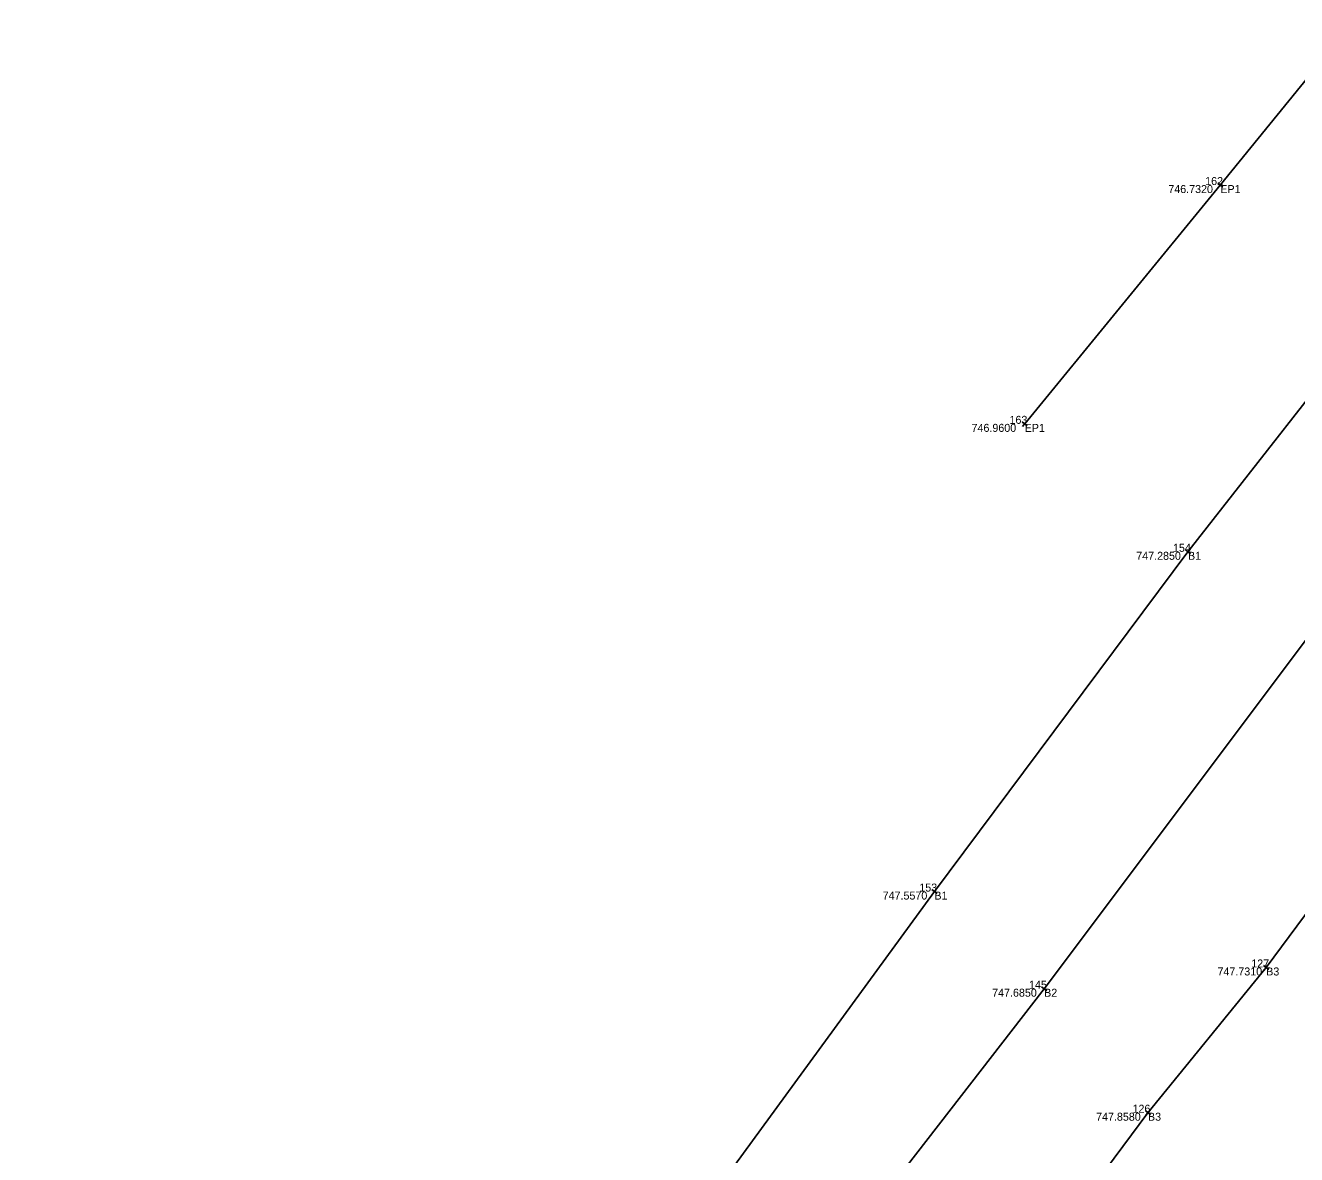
# Model space of a CAD drawing. Extents: x 1857337 to 1857837, y 693958 to 694371.
# Drawn here: x 1857509.4 to 1857604.7, y 694201.5 to 694286.2 of the extents above; entities that cross this region are included whole.
import ezdxf

# ---------------------------------------------------------------- set-up
doc = ezdxf.new("R2010")
doc.units = 0
for name, color, linetype in [('BR_X_SV_Pier_Cap_Bottom', 7, 'Continuous'), ('SV_X_Random_Point', 7, 'Continuous'), ('SV_X_Text_Comment', 7, 'Continuous'), ('SV_X_Text_Description', 7, 'Continuous'), ('SV_X_Text_Name', 7, 'Continuous'), ('UT_X_Electric_Cells', 7, 'Continuous')]:
    doc.layers.add(name, color=color, linetype=linetype)

msp = doc.modelspace()

# ---------------------------------------------------------------- linework, layer by layer
at = {"layer": 'BR_X_SV_Pier_Cap_Bottom'}
for p, q in [((1857599.173, 694274.033), (1857598.785, 694274.349)), ((1857599.137, 694274.385), (1857598.821, 694273.997)), ((1857598.979, 694274.191), (1857598.979, 694274.191)), ((1857584.508, 694256.125), (1857584.122, 694256.441)), ((1857584.473, 694256.476), (1857584.157, 694256.09)), ((1857584.315, 694256.283), (1857584.315, 694256.283)), ((1857596.755, 694246.534), (1857596.361, 694246.842)), ((1857596.712, 694246.885), (1857596.404, 694246.491)), ((1857596.558, 694246.688), (1857596.558, 694246.688)), ((1857577.747, 694221.059), (1857577.347, 694221.358)), ((1857577.697, 694221.408), (1857577.397, 694221.008)), ((1857577.547, 694221.208), (1857577.547, 694221.208)), ((1857602.621, 694215.368), (1857602.219, 694215.666)), ((1857602.569, 694215.718), (1857602.271, 694215.316)), ((1857602.42, 694215.517), (1857602.42, 694215.517)), ((1857585.974, 694213.773), (1857585.574, 694214.073)), ((1857585.924, 694214.123), (1857585.624, 694213.723)), ((1857585.774, 694213.923), (1857585.774, 694213.923)), ((1857593.751, 694204.465), (1857593.363, 694204.781)), ((1857593.715, 694204.817), (1857593.399, 694204.429)), ((1857593.557, 694204.623), (1857593.557, 694204.623))]:
    msp.add_line(p, q, dxfattribs=at)
at = {"layer": 'SV_X_Random_Point'}
msp.add_lwpolyline([(1857678.612, 694370.843), (1857656.803, 694344.014), (1857632.513, 694313.441), (1857612.984, 694291.43), (1857598.979, 694274.191), (1857584.315, 694256.283)], dxfattribs=at)
at = {"layer": 'UT_X_Electric_Cells'}
for points in [[(1857688.755, 694366.464), (1857664.256, 694336.576), (1857640.398, 694304.002), (1857624.286, 694283.662), (1857611.111, 694265.289), (1857596.558, 694246.688), (1857577.547, 694221.208), (1857552.759, 694187.231), (1857529.482, 694157.726), (1857506.444, 694129.202)], [(1857700.074, 694362.042), (1857689.247, 694348.993), (1857682.836, 694339.855), (1857667.65, 694320.725), (1857658.449, 694307.697), (1857647.304, 694293.665), (1857639.922, 694285.279), (1857631.254, 694272.579), (1857620.537, 694259.563), (1857609.95, 694246.134), (1857585.774, 694213.923), (1857569.943, 694193.463), (1857560.421, 694180.388), (1857538.657, 694151.419), (1857515.128, 694123.122)], [(1857711.16, 694357.223), (1857703.201, 694345.955), (1857690.712, 694330.845), (1857675.141, 694311.606), (1857665.25, 694297.054), (1857650.194, 694279.109), (1857639.816, 694265.056), (1857626.459, 694247.565), (1857616.276, 694234.207), (1857602.42, 694215.517), (1857593.557, 694204.623), (1857579.141, 694185.197), (1857570.864, 694174.066), (1857548.438, 694145.748), (1857525.385, 694115.504)]]:
    msp.add_lwpolyline(points, dxfattribs=at)

# ---------------------------------------------------------------- texts
at = {"layer": 'SV_X_Text_Comment'}
for s, p in [('EP1', (1857598.979, 694273.591)), ('EP1', (1857584.315, 694255.683)), ('B1', (1857596.558, 694246.088)), ('B1', (1857577.547, 694220.608)), ('B3', (1857602.42, 694214.917)), ('B2', (1857585.774, 694213.323)), ('B3', (1857593.557, 694204.023))]:
    msp.add_text(s, height=0.6, dxfattribs=at).set_placement(p)
at = {"layer": 'SV_X_Text_Description'}
for s, p in [('746.7320', (1857595.082, 694273.591)), ('746.9600', (1857580.333, 694255.683)), ('747.2850', (1857592.68, 694246.088)), ('747.5570', (1857573.669, 694220.608)), ('747.7310', (1857598.769, 694214.917)), ('747.6850', (1857581.877, 694213.323)), ('747.8580', (1857589.669, 694204.023))]:
    msp.add_text(s, height=0.6, dxfattribs=at).set_placement(p)
at = {"layer": 'SV_X_Text_Name'}
for s, p in [('162', (1857597.846, 694274.191)), ('163', (1857583.177, 694256.283)), ('154', (1857595.434, 694246.688)), ('153', (1857576.418, 694221.208)), ('127', (1857601.301, 694215.517)), ('145', (1857584.641, 694213.923)), ('126', (1857592.4, 694204.623))]:
    msp.add_text(s, height=0.6, dxfattribs=at).set_placement(p)

doc.saveas('drawing.dxf')
